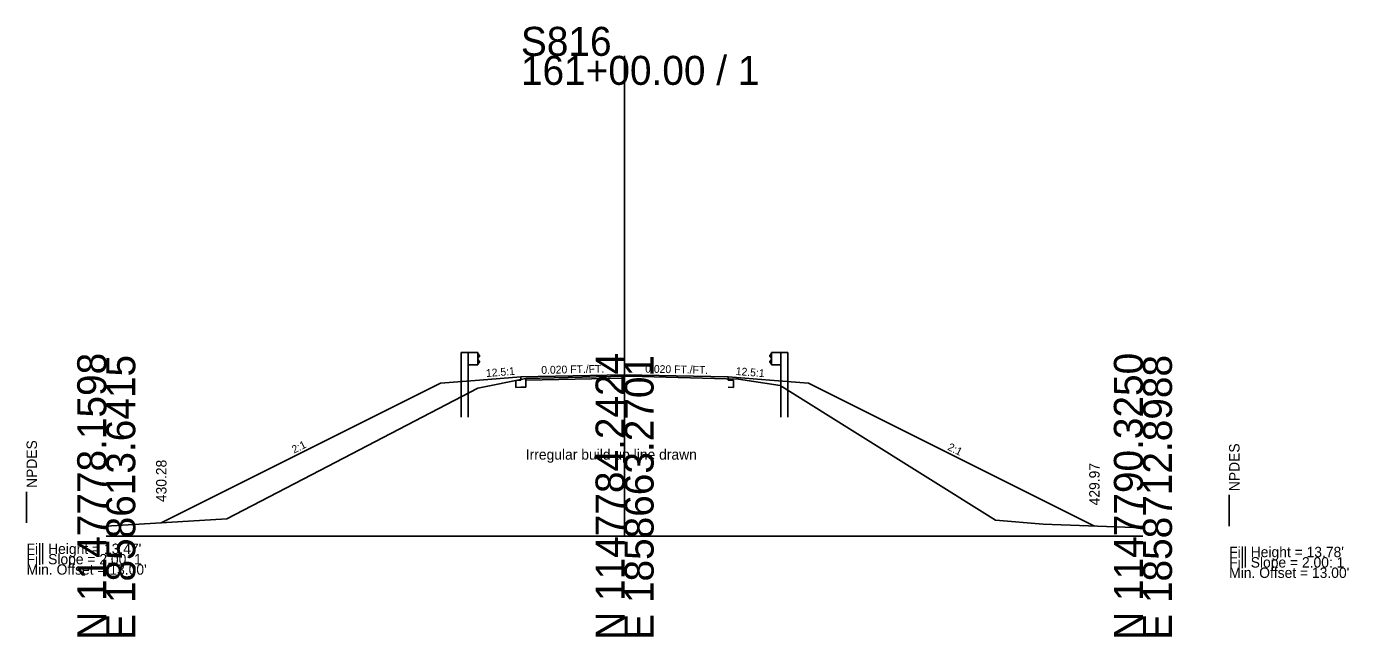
# Model space of a CAD drawing. Extents: x -76 to 4323, y -10 to 2055.
# Drawn here: x 992.3 to 1119.8, y 1490.3 to 1549.2 of the extents above; entities that cross this region are included whole.
import ezdxf

# ---------------------------------------------------------------- set-up
doc = ezdxf.new("R2010")
doc.units = 0
for name, color, linetype in [('Default', 7, 'Continuous'), ('RD_GPK_XS_Cell', 7, 'Continuous'), ('RD_XS_Base', 7, 'Continuous'), ('RD_XS_Buildup', 7, 'Continuous'), ('RD_XS_EarthShd', 7, 'Continuous'), ('RD_XS_ExGround', 7, 'Continuous'), ('RD_XS_GR', 7, 'Continuous'), ('RD_XS_NPDES', 7, 'Continuous'), ('RD_XS_Pave', 7, 'Continuous'), ('RD_XS_TieSlope', 7, 'Continuous'), ('RD_XS_TX_Elev_PR', 7, 'Continuous'), ('RD_XS_TX_ShdSlope', 7, 'Continuous'), ('RD_XS_TX_Slope', 7, 'Continuous'), ('RD_XS_TX_Warning', 7, 'Continuous')]:
    doc.layers.add(name, color=color, linetype=linetype)

msp = doc.modelspace()

# ---------------------------------------------------------------- linework, layer by layer
at = {"layer": 'Default'}
for p, q in [((1040, 1515.37), (1050, 1515.57)), ((1050, 1515.57), (1060, 1515.37))]:
    msp.add_line(p, q, dxfattribs=at)
at = {"layer": 'RD_GPK_XS_Cell'}
for p, q in [((1050, 1500), (1050, 1546.35)), ((1000, 1500), (1050, 1500)), ((1050, 1500), (1100, 1500))]:
    msp.add_line(p, q, dxfattribs=at)
at = {"layer": 'RD_XS_Base'}
for p, q in [((1040.47, 1514.38), (1040.47, 1515.21)), ((1040.47, 1514.38), (1040.47, 1515.21)), ((1040, 1514.37), (1040.47, 1514.38)), ((1040, 1514.37), (1040.47, 1514.38))]:
    msp.add_line(p, q, dxfattribs=at)
at = {"layer": 'RD_XS_Buildup'}
msp.add_line((1040.47, 1515.05), (1050, 1515.24), dxfattribs=at)
msp.add_line((1040.47, 1515.05), (1050, 1515.24), dxfattribs=at)
at = {"layer": 'RD_XS_EarthShd'}
for p, q in [((1040, 1515.37), (1036, 1515.05)), ((1040, 1515.37), (1036, 1515.05)), ((1060, 1515.37), (1064, 1515.05)), ((1060, 1515.37), (1064, 1515.05)), ((1036, 1515.05), (1032.25, 1514.75)), ((1036, 1515.05), (1032.25, 1514.75)), ((1064, 1515.05), (1067.75, 1514.75)), ((1064, 1515.05), (1067.75, 1514.75))]:
    msp.add_line(p, q, dxfattribs=at)
at = {"layer": 'RD_XS_ExGround'}
for p, q in [((1035.84, 1514.27), (1040.47, 1515.21)), ((1040.47, 1515.21), (1050, 1515.44)), ((1050, 1515.44), (1050.55, 1515.45)), ((1050.55, 1515.45), (1061, 1515.16)), ((1061, 1515.16), (1065.01, 1514.55)), ((1020.6, 1506.33), (1035.84, 1514.27)), ((1065.01, 1514.55), (1065.67, 1514.12)), ((1065.67, 1514.12), (1085.78, 1501.53)), ((1011.62, 1501.66), (1020.6, 1506.33)), ((1000, 1500.97), (1011.62, 1501.66)), ((1085.78, 1501.53), (1090.37, 1501.14)), ((1090.37, 1501.14), (1100, 1500.8))]:
    msp.add_line(p, q, dxfattribs=at)
at = {"layer": 'RD_XS_GR'}
for p, q in [((1034.25, 1517.71), (1034.25, 1514.91)), ((1034.92, 1517.71), (1034.25, 1517.71)), ((1034.25, 1517.71), (1034.25, 1514.91)), ((1034.92, 1517.71), (1034.25, 1517.71)), ((1034.92, 1517.71), (1034.92, 1514.96)), ((1035.83, 1517.71), (1034.92, 1517.71)), ((1034.92, 1517.71), (1034.92, 1514.96)), ((1035.83, 1517.71), (1034.92, 1517.71)), ((1035.83, 1516.54), (1034.92, 1516.54)), ((1035.83, 1516.54), (1034.92, 1516.54)), ((1035.83, 1516.54), (1035.83, 1517.71)), ((1035.83, 1516.54), (1035.83, 1517.71)), ((1035.83, 1517.63), (1036, 1517.43)), ((1035.83, 1517.63), (1036, 1517.43)), ((1036, 1517.38), (1035.83, 1517.18)), ((1036, 1517.38), (1035.83, 1517.18)), ((1036, 1516.86), (1035.83, 1517.06)), ((1036, 1516.86), (1035.83, 1517.06)), ((1035.83, 1516.61), (1036, 1516.81)), ((1035.83, 1516.61), (1036, 1516.81)), ((1036, 1517.43), (1036, 1517.38)), ((1036, 1517.43), (1036, 1517.38)), ((1036, 1516.81), (1036, 1516.86)), ((1036, 1516.81), (1036, 1516.86)), ((1064.17, 1517.63), (1064, 1517.43)), ((1064.17, 1517.63), (1064, 1517.43)), ((1064, 1517.43), (1064, 1517.38)), ((1064, 1517.43), (1064, 1517.38)), ((1064, 1517.38), (1064.17, 1517.18)), ((1064, 1517.38), (1064.17, 1517.18)), ((1064, 1516.86), (1064.17, 1517.06)), ((1064, 1516.86), (1064.17, 1517.06)), ((1064, 1516.81), (1064, 1516.86)), ((1064, 1516.81), (1064, 1516.86)), ((1064.17, 1516.61), (1064, 1516.81)), ((1064.17, 1516.61), (1064, 1516.81)), ((1064.17, 1516.54), (1064.17, 1517.71)), ((1064.17, 1517.71), (1065.08, 1517.71)), ((1064.17, 1516.54), (1064.17, 1517.71)), ((1064.17, 1517.71), (1065.08, 1517.71)), ((1064.17, 1516.54), (1065.08, 1516.54)), ((1064.17, 1516.54), (1065.08, 1516.54)), ((1065.08, 1517.71), (1065.08, 1514.96)), ((1065.08, 1517.71), (1065.75, 1517.71)), ((1065.08, 1517.71), (1065.08, 1514.96)), ((1065.08, 1517.71), (1065.75, 1517.71)), ((1065.75, 1517.71), (1065.75, 1514.91)), ((1065.75, 1517.71), (1065.75, 1514.91)), ((1034.25, 1514.91), (1034.25, 1511.49)), ((1034.25, 1514.91), (1034.25, 1511.49)), ((1034.92, 1511.49), (1034.92, 1514.96)), ((1034.92, 1511.49), (1034.92, 1514.96)), ((1065.08, 1511.49), (1065.08, 1514.96)), ((1065.08, 1511.49), (1065.08, 1514.96)), ((1065.75, 1514.91), (1065.75, 1511.49)), ((1065.75, 1514.91), (1065.75, 1511.49))]:
    msp.add_line(p, q, dxfattribs=at)
at = {"layer": 'RD_XS_NPDES'}
for p, q in [((992.31, 1501.28), (992.31, 1504.28)), ((992.31, 1501.28), (992.31, 1504.28)), ((1108.32, 1500.97), (1108.32, 1503.97)), ((1108.32, 1500.97), (1108.32, 1503.97))]:
    msp.add_line(p, q, dxfattribs=at)
at = {"layer": 'RD_XS_Pave'}
for p, q in [((1040, 1515.04), (1040, 1515.37)), ((1040, 1515.04), (1040, 1515.37)), ((1060, 1515.04), (1060, 1515.37)), ((1060, 1515.04), (1060, 1515.37)), ((1039.5, 1515.03), (1040, 1515.04)), ((1039.5, 1515.03), (1040, 1515.04)), ((1039.5, 1514.36), (1039.5, 1515.03)), ((1039.5, 1514.36), (1039.5, 1515.03)), ((1040, 1514.37), (1039.5, 1514.36)), ((1040, 1514.37), (1039.5, 1514.36)), ((1060.5, 1515.03), (1060, 1515.04)), ((1060.5, 1515.03), (1060, 1515.04)), ((1060, 1514.37), (1060.5, 1514.36)), ((1060, 1514.37), (1060.5, 1514.36)), ((1060.5, 1514.36), (1060.5, 1515.03)), ((1060.5, 1514.36), (1060.5, 1515.03))]:
    msp.add_line(p, q, dxfattribs=at)
at = {"layer": 'RD_XS_TieSlope'}
for p, q in [((1032.25, 1514.75), (1005.31, 1501.28)), ((1032.25, 1514.75), (1005.31, 1501.28)), ((1067.75, 1514.75), (1095.32, 1500.97)), ((1067.75, 1514.75), (1095.32, 1500.97))]:
    msp.add_line(p, q, dxfattribs=at)

# ---------------------------------------------------------------- texts
at = {"layer": 'RD_GPK_XS_Cell'}
for s, p in [('S816', (1040, 1546.35)), ('161+00.00 / 1', (1040, 1543.55))]:
    msp.add_text(s, height=2.8, dxfattribs=at).set_placement(p)
for s, p in [('N 1147778.1598', (1000, 1490)), ('E 1858613.6415', (1002.8, 1490)), ('N 1147784.2424', (1050, 1490)), ('E 1858663.2701', (1052.8, 1490)), ('N 1147790.3250', (1100, 1490)), ('E 1858712.8988', (1102.8, 1490))]:
    msp.add_text(s, height=2.8, rotation=90, dxfattribs=at).set_placement(p)
at = {"layer": 'RD_XS_TX_Elev_PR'}
for s, p in [('430.28', (1005.81, 1503.28)), ('430.28', (1005.81, 1503.28)), ('429.97', (1095.82, 1502.97)), ('429.97', (1095.82, 1502.97))]:
    msp.add_text(s, height=1, rotation=90, dxfattribs=at).set_placement(p)
at = {"layer": 'RD_XS_TX_ShdSlope'}
for rotation, p in [(4.5739, (1036.66, 1515.35)), (4.5739, (1036.66, 1515.35)), (355.4261, (1060.7, 1515.56)), (355.4261, (1060.7, 1515.56))]:
    msp.add_text('12.5:1', height=0.75, rotation=rotation, dxfattribs=at).set_placement(p)
at = {"layer": 'RD_XS_TX_Slope'}
for s, rotation, p in [('0.020 FT./FT.', 1.1458, (1041.97, 1515.66)), ('0.020 FT./FT.', 1.1458, (1041.97, 1515.66)), ('0.020 FT./FT.', 358.8542, (1051.98, 1515.78)), ('0.020 FT./FT.', 358.8542, (1051.98, 1515.78)), ('2:1', 26.5651, (1018.12, 1507.96)), ('2:1', 26.5651, (1018.12, 1507.96)), ('2:1', 333.4349, (1081.09, 1508.36)), ('2:1', 333.4349, (1081.09, 1508.36))]:
    msp.add_text(s, height=0.75, rotation=rotation, dxfattribs=at).set_placement(p)
at = {"layer": 'RD_XS_TX_Warning'}
for p in [(993.31, 1504.28), (993.31, 1504.28), (1109.32, 1503.97), (1109.32, 1503.97)]:
    msp.add_text(' NPDES', height=1, rotation=90, dxfattribs=at).set_placement(p)
for s, p in [('Irregular build up line drawn', (1040.47, 1507.38)), ('Irregular build up line drawn', (1040.47, 1507.38)), ("Fill Height = 13.47' ", (992.31, 1498.28)), ("Fill Height = 13.47' ", (992.31, 1498.28)), ("Fill Height = 13.78' ", (1108.32, 1497.97)), ("Fill Height = 13.78' ", (1108.32, 1497.97)), ('Fill Slope = 2.00: 1', (992.31, 1497.28)), ('Fill Slope = 2.00: 1', (992.31, 1497.28)), ("Min. Offset = 13.00' ", (992.31, 1496.28)), ("Min. Offset = 13.00' ", (992.31, 1496.28)), ('Fill Slope = 2.00: 1', (1108.32, 1496.97)), ('Fill Slope = 2.00: 1', (1108.32, 1496.97)), ("Min. Offset = 13.00' ", (1108.32, 1495.97)), ("Min. Offset = 13.00' ", (1108.32, 1495.97))]:
    msp.add_text(s, height=1, dxfattribs=at).set_placement(p)

doc.saveas('drawing.dxf')
